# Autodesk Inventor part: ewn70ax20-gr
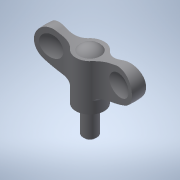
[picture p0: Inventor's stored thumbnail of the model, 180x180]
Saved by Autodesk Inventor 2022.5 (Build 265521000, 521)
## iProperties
Created: 2016-12
Part Number: ewn70ax20-gr
Material: 一般
Document SubType Name: Modeling
Designer: imaocorp
Density: 1 g/cm^3
Appearance: 既定
Author: imaocorp
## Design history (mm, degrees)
node "ewn70ax20-gr.x_t1"
node "ewn70ax20-gr"
node "Base1"
